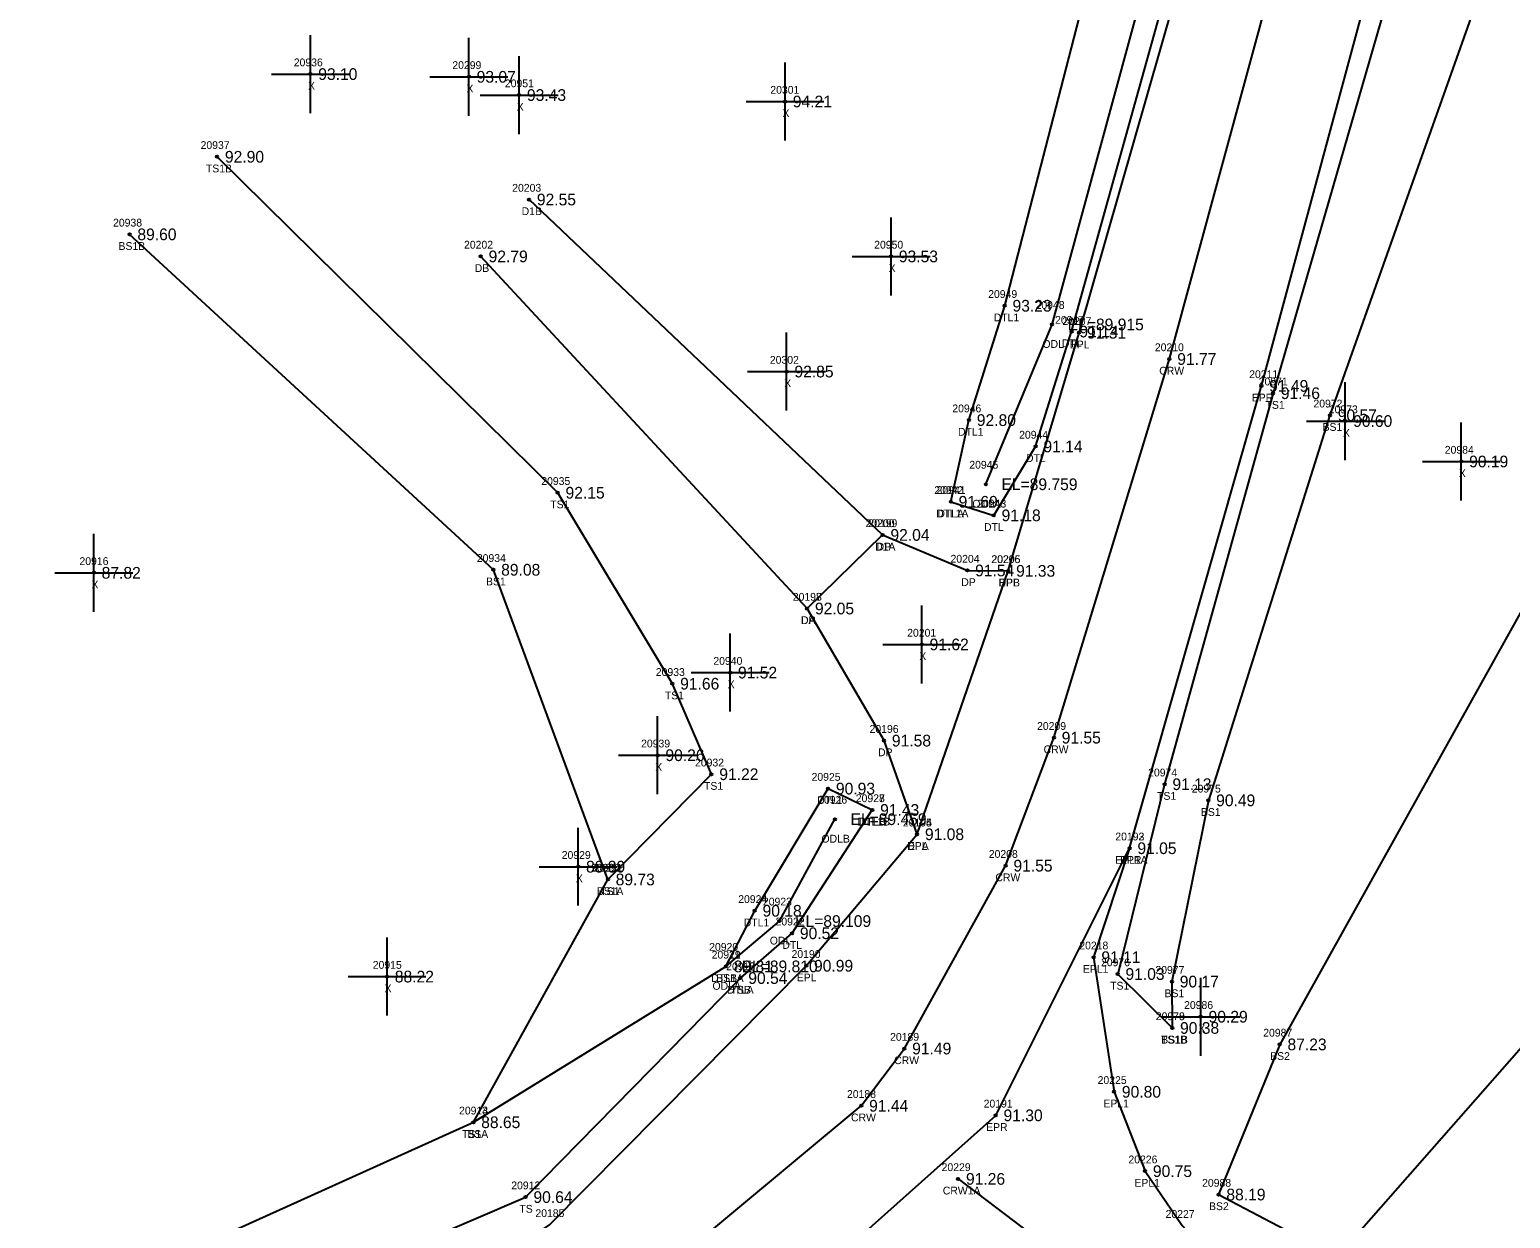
# Model space of a CAD drawing. Extents: x 2530197 to 2532051, y 935230 to 936631.
# Drawn here: x 2531647.6 to 2531837.5, y 936328 to 936480.5 of the extents above; entities that cross this region are included whole.
import ezdxf

# ---------------------------------------------------------------- set-up
doc = ezdxf.new("R2010")
doc.units = 0
for name, color, linetype in [('RD_DTM_BkLn1', 7, 'Continuous'), ('RD_DTM_BkLn2', 7, 'Continuous'), ('RD_DTM_BkLn_txCode', 7, 'Continuous'), ('RD_EX_Driveway', 7, 'Continuous'), ('RD_EX_Driveway_txCode', 7, 'Continuous'), ('RD_EX_H2O', 7, 'Continuous'), ('RD_EX_H2O_txCode', 7, 'Continuous'), ('RD_EX_Misc', 7, 'Continuous'), ('RD_EX_Misc_txCode', 7, 'Continuous'), ('RD_EX_Road', 7, 'Continuous'), ('RD_EX_Road_txCode', 7, 'Continuous'), ('RD_EX_TX_Driveway_ELEV', 7, 'Continuous'), ('RD_EX_TX_H2O_ELEV', 7, 'Continuous'), ('RD_EX_TX_Misc_ELEV', 7, 'Continuous'), ('RD_EX_TX_Road_ELEV', 7, 'Continuous'), ('RD_HC_Survey_ELEV', 7, 'Continuous'), ('RD_HC_Survey_txCode', 7, 'Continuous'), ('RD_SMD_Locator', 7, 'Continuous')]:
    doc.layers.add(name, color=color, linetype=linetype)

msp = doc.modelspace()

# ---------------------------------------------------------------- linework, layer by layer
at = {"layer": 'RD_DTM_BkLn1'}
for points in [[(2531175.16, 935992.09), (2531214.08, 936014.93), (2531297.2, 936064.16), (2531382.2, 936114.3), (2531466.12, 936163.77), (2531548.89, 936212.96), (2531632.55, 936261.89), (2531678, 936289.19), (2531722.34, 936315.93), (2531754.26, 936342.49), (2531759.78, 936349.83), (2531772.77, 936373.29), (2531778.96, 936389.71), (2531793.78, 936438.29), (2531813.65, 936511.36), (2531832.39, 936582.88)], [(2531766.68, 936333.11), (2531794.16, 936312.25), (2531844.23, 936274.13), (2531924.38, 936213.25), (2532005.14, 936152.12)]]:
    msp.add_lwpolyline(points, dxfattribs=at)
at = {"layer": 'RD_DTM_BkLn2'}
for points in [[(2531847.31, 936578.71), (2531828.5, 936507.99), (2531807.07, 936433.9), (2531793.16, 936383.74), (2531787.14, 936359.39), (2531794.14, 936352.47)], [(2531858.76, 936574.82), (2531840.28, 936504.17), (2531814.37, 936431.07), (2531798.77, 936381.67), (2531794.1, 936358.42), (2531794.14, 936352.47)], [(2531917.54, 936550.96), (2531882.37, 936485.34), (2531845.03, 936416.88), (2531807.92, 936350.36), (2531800.08, 936331.1), (2531815.28, 936323.11), (2531842.04, 936353.56), (2531870.4, 936350.41), (2531903.53, 936402.83), (2531942.77, 936461.82), (2531965.7, 936452.8), (2531970.35, 936457.79), (2531954.01, 936477.47), (2531964.77, 936498.69)], [(2531704.5, 936340.37), (2531721.75, 936371.52), (2531735.04, 936385.02), (2531730.02, 936396.63), (2531715.32, 936421.13), (2531671.63, 936464.23)], [(2531721.75, 936371.52), (2531707.06, 936411.25), (2531660.4, 936454.28)], [(2531549.3, 936252.1), (2531614.51, 936292.5), (2531672.61, 936325.97), (2531704.5, 936340.37), (2531736.9, 936360.37)], [(2531551.68, 936248.23), (2531617.31, 936287.8), (2531672.2, 936319.81), (2531679.05, 936316.94), (2531711.2, 936330.77), (2531738.76, 936358.87)]]:
    msp.add_lwpolyline(points, dxfattribs=at)
at = {"layer": 'RD_EX_Driveway'}
for p, q in [((2531756.99, 936415.72), (2531711.64, 936458.75)), ((2531747.31, 936406.28), (2531705.45, 936451.45))]:
    msp.add_line(p, q, dxfattribs=at)
msp.add_lwpolyline([(2531761.42, 936377.32), (2531757.18, 936389.33), (2531747.31, 936406.28), (2531756.99, 936415.72), (2531767.86, 936411.16), (2531773.11, 936411.11)], dxfattribs=at)
at = {"layer": 'RD_EX_H2O'}
for points in [[(2531765.74, 936419.97), (2531768.07, 936430.45), (2531772.65, 936445.12), (2531791.42, 936517.8), (2531810.23, 936589.19)], [(2531765.74, 936419.97), (2531771.25, 936418.23), (2531776.62, 936427.07), (2531781.23, 936441.81), (2531801.62, 936515.08), (2531818.73, 936586.25)], [(2531770.23, 936422.22), (2531778.73, 936442.72), (2531798.67, 936515.95), (2531816.58, 936587.11)], [(2531736.9, 936360.37), (2531740.59, 936367.5), (2531750, 936383.18), (2531755.67, 936380.44)], [(2531736.9, 936360.37), (2531743.76, 936366.18), (2531750.87, 936379.25)], [(2531738.76, 936358.87), (2531745.38, 936364.62), (2531755.67, 936380.44)]]:
    msp.add_lwpolyline(points, dxfattribs=at)
at = {"layer": 'RD_EX_Misc'}
for p, q in [((2531683.6, 936469.84), (2531683.6, 936479.84)), ((2531703.92, 936469.49), (2531703.92, 936479.49)), ((2531710.37, 936467.15), (2531710.37, 936477.15)), ((2531744.47, 936466.32), (2531744.47, 936476.32)), ((2531678.6, 936474.84), (2531688.6, 936474.84)), ((2531698.92, 936474.49), (2531708.92, 936474.49)), ((2531705.37, 936472.15), (2531715.37, 936472.15)), ((2531739.47, 936471.32), (2531749.47, 936471.32)), ((2531758.07, 936446.45), (2531758.07, 936456.45)), ((2531753.07, 936451.45), (2531763.07, 936451.45)), ((2531744.68, 936431.68), (2531744.68, 936441.68)), ((2531739.68, 936436.68), (2531749.68, 936436.68)), ((2531816.34, 936425.33), (2531816.34, 936435.33)), ((2531811.34, 936430.33), (2531821.34, 936430.33)), ((2531831.22, 936420.14), (2531831.22, 936430.14)), ((2531826.22, 936425.14), (2531836.22, 936425.14)), ((2531655.82, 936405.86), (2531655.82, 936415.86)), ((2531650.82, 936410.86), (2531660.82, 936410.86)), ((2531762.02, 936396.67), (2531762.02, 936406.67)), ((2531737.44, 936393.06), (2531737.44, 936403.06)), ((2531757.02, 936401.67), (2531767.02, 936401.67)), ((2531732.44, 936398.06), (2531742.44, 936398.06)), ((2531728.13, 936382.46), (2531728.13, 936392.46)), ((2531723.13, 936387.46), (2531733.13, 936387.46)), ((2531717.95, 936368.16), (2531717.95, 936378.16)), ((2531712.95, 936373.16), (2531722.95, 936373.16)), ((2531693.42, 936354.06), (2531693.42, 936364.06)), ((2531688.42, 936359.06), (2531698.42, 936359.06)), ((2531797.8, 936348.91), (2531797.8, 936358.91)), ((2531792.8, 936353.91), (2531802.8, 936353.91))]:
    msp.add_line(p, q, dxfattribs=at)
at = {"layer": 'RD_EX_Road'}
for points in [[(2531169.65, 936000.77), (2531208.79, 936024.95), (2531292.04, 936074.02), (2531376.24, 936123.7), (2531460.37, 936174.49), (2531542.92, 936223.44), (2531626.67, 936270.85), (2531672.4, 936298.39), (2531714.28, 936327.21), (2531747.19, 936360.45), (2531761.42, 936377.32), (2531773.11, 936411.11), (2531782.2, 936441.65), (2531803.17, 936514.76), (2531820.28, 936585.8)], [(2531180.82, 935982), (2531220.82, 936004.21), (2531303.54, 936053.39), (2531388.75, 936103.71), (2531472.27, 936152.98), (2531554.79, 936201.9), (2531638.11, 936250.92), (2531683.19, 936278.28), (2531730.37, 936304.55), (2531771.5, 936341.26), (2531788.67, 936375.53), (2531805.57, 936434.84), (2531825.53, 936508.74), (2531844.13, 936579.65)], [(2531788.67, 936375.53), (2531784.05, 936361.55), (2531786.68, 936344.28), (2531790.66, 936334.1), (2531795.41, 936327.11), (2531801.08, 936320.84), (2531849.6, 936283.17), (2531876.01, 936264.22), (2531894.71, 936249.13), (2531930.69, 936221.59), (2532010.91, 936160.51)]]:
    msp.add_lwpolyline(points, dxfattribs=at)
at = {"layer": 'RD_SMD_Locator'}
for centre in [(2531683.6, 936474.84), (2531703.92, 936474.49), (2531710.37, 936472.15), (2531744.47, 936471.32), (2531671.63, 936464.23), (2531711.64, 936458.75), (2531660.4, 936454.28), (2531705.45, 936451.45), (2531758.07, 936451.45), (2531772.65, 936445.12), (2531778.73, 936442.72), (2531781.23, 936441.81), (2531782.2, 936441.65), (2531793.78, 936438.29), (2531744.68, 936436.68), (2531805.57, 936434.84), (2531807.07, 936433.9), (2531768.07, 936430.45), (2531814.37, 936431.07), (2531816.34, 936430.33), (2531776.62, 936427.07), (2531831.22, 936425.14), (2531715.32, 936421.13), (2531770.23, 936422.22), (2531765.74, 936419.97), (2531765.74, 936419.97), (2531771.25, 936418.23), (2531756.99, 936415.72), (2531756.99, 936415.72), (2531707.06, 936411.25), (2531655.82, 936410.86), (2531767.86, 936411.16), (2531773.11, 936411.11), (2531773.11, 936411.11), (2531747.31, 936406.28), (2531747.31, 936406.28), (2531762.02, 936401.67), (2531737.44, 936398.06), (2531730.02, 936396.63), (2531757.18, 936389.33), (2531778.96, 936389.71), (2531728.13, 936387.46), (2531735.04, 936385.02), (2531750, 936383.18), (2531793.16, 936383.74), (2531798.77, 936381.67), (2531750.87, 936379.25), (2531755.67, 936380.44), (2531755.67, 936380.44), (2531761.42, 936377.32), (2531761.42, 936377.32), (2531788.67, 936375.53), (2531788.67, 936375.53), (2531772.77, 936373.29), (2531717.95, 936373.16), (2531721.75, 936371.52), (2531721.75, 936371.52), (2531740.59, 936367.5), (2531743.76, 936366.18), (2531745.38, 936364.62), (2531736.9, 936360.37), (2531736.9, 936360.37), (2531736.9, 936360.37), (2531747.19, 936360.45), (2531784.05, 936361.55), (2531693.42, 936359.06), (2531738.76, 936358.87), (2531738.76, 936358.87), (2531787.14, 936359.39), (2531794.1, 936358.42), (2531794.14, 936352.47), (2531794.14, 936352.47), (2531797.8, 936353.91), (2531759.78, 936349.83), (2531807.92, 936350.36), (2531786.68, 936344.28), (2531754.26, 936342.49), (2531771.5, 936341.26), (2531704.5, 936340.37), (2531704.5, 936340.37), (2531790.66, 936334.1), (2531766.68, 936333.11), (2531711.2, 936330.77), (2531800.08, 936331.1)]:
    msp.add_circle(centre, 0.15, dxfattribs=at)

# ---------------------------------------------------------------- texts
at = {"layer": 'RD_DTM_BkLn_txCode'}
for s, p in [('20937', (2531669.51, 936465.23)), ('TS1B', (2531670.19, 936462.23)), ('20938', (2531658.28, 936455.28)), ('BS1B', (2531658.98, 936452.28)), ('20971', (2531805.23, 936434.9)), ('TS1', (2531806.11, 936431.9)), ('20972', (2531812.25, 936432.07)), ('BS1', (2531813.43, 936429.07)), ('20935', (2531713.21, 936422.13)), ('TS1', (2531714.36, 936419.13)), ('20934', (2531704.94, 936412.25)), ('BS1', (2531706.12, 936409.25)), ('20933', (2531727.9, 936397.63)), ('TS1', (2531729.06, 936394.63)), ('20932', (2531732.93, 936386.02)), ('20974', (2531791.05, 936384.74)), ('TS1', (2531734.08, 936383.02)), ('20975', (2531796.65, 936382.67)), ('TS1', (2531792.2, 936381.74)), ('BS1', (2531797.82, 936379.67)), ('20930', (2531719.6, 936372.52)), ('20931', (2531719.92, 936372.52)), ('BS1A', (2531720.32, 936369.52)), ('TS1', (2531720.79, 936369.52)), ('20919', (2531735.06, 936361.37)), ('20917', (2531736.93, 936359.87)), ('20976', (2531785, 936360.39)), ('20977', (2531791.98, 936359.42)), ('BSB', (2531735.65, 936358.37)), ('TS1', (2531786.18, 936357.39)), ('TSB', (2531737.49, 936356.87)), ('BS1', (2531793.15, 936356.42)), ('20978', (2531792.03, 936353.47)), ('20979', (2531792.03, 936353.47)), ('TS1B', (2531792.71, 936350.47)), ('BS1B', (2531792.73, 936350.47)), ('20987', (2531805.81, 936351.36)), ('BS2', (2531806.7, 936348.36)), ('20913', (2531702.66, 936341.37)), ('20914', (2531702.66, 936341.37)), ('TS1A', (2531703.05, 936338.37)), ('BS', (2531703.72, 936338.37)), ('20912', (2531709.36, 936331.77)), ('20988', (2531797.97, 936332.1)), ('TS', (2531710.4, 936328.77)), ('BS2', (2531798.86, 936329.1))]:
    msp.add_text(s, height=1, dxfattribs=at).set_placement(p)
at = {"layer": 'RD_EX_Driveway_txCode'}
for s, p in [('20203', (2531709.48, 936459.75)), ('D1B', (2531710.69, 936456.75)), ('20202', (2531703.3, 936452.45)), ('DB', (2531704.67, 936449.45)), ('20200', (2531754.8, 936416.72)), ('20199', (2531755.16, 936416.72)), ('D1A', (2531756.03, 936413.72)), ('DP', (2531756.21, 936413.72)), ('20204', (2531765.7, 936412.16)), ('20205', (2531770.96, 936412.11)), ('DP', (2531767.08, 936409.16)), ('DPB', (2531771.86, 936409.11)), ('20197', (2531745.47, 936407.28)), ('20198', (2531745.47, 936407.28)), ('DA', (2531746.51, 936404.28)), ('DP', (2531746.53, 936404.28)), ('20196', (2531755.32, 936390.33)), ('DP', (2531756.4, 936387.33)), ('20195', (2531759.59, 936378.32)), ('DPA', (2531760.15, 936375.32))]:
    msp.add_text(s, height=1, dxfattribs=at).set_placement(p)
at = {"layer": 'RD_EX_H2O_txCode'}
for s, p in [('20949', (2531770.53, 936446.12)), ('20948', (2531776.61, 936444.72)), ('DTL1', (2531771.24, 936443.12)), ('20947', (2531779.11, 936442.81)), ('ODL', (2531777.49, 936439.72)), ('DTL', (2531779.99, 936439.81)), ('20946', (2531765.93, 936431.45)), ('DTL1', (2531766.66, 936428.45)), ('20944', (2531774.5, 936428.07)), ('20945', (2531768.11, 936424.22)), ('DTL', (2531775.38, 936425.07)), ('20942', (2531763.62, 936420.97)), ('20941', (2531763.91, 936420.97)), ('ODLA', (2531768.5, 936419.22)), ('20943', (2531769.13, 936419.23)), ('DTL1A', (2531763.84, 936417.97)), ('DTLA', (2531764.01, 936417.97)), ('DTL', (2531770, 936416.23)), ('20925', (2531747.88, 936384.18)), ('DTL1', (2531748.59, 936381.18)), ('20926', (2531748.72, 936381.25)), ('20927', (2531753.55, 936381.44)), ('20928', (2531753.55, 936381.44)), ('DTL1B', (2531753.78, 936378.44)), ('DTLB', (2531753.95, 936378.44)), ('ODLB', (2531749.15, 936376.25)), ('20924', (2531738.47, 936368.5)), ('20923', (2531741.64, 936368.18)), ('DTL1', (2531739.18, 936365.5)), ('20922', (2531743.26, 936365.62)), ('ODL', (2531742.52, 936363.18)), ('20920', (2531734.74, 936362.37)), ('20921', (2531735.06, 936361.37)), ('DTL', (2531744.13, 936362.62)), ('20918', (2531736.93, 936359.87)), ('DTL1A', (2531735, 936358.37)), ('ODLA', (2531735.17, 936357.37)), ('DTLA', (2531737.03, 936356.87))]:
    msp.add_text(s, height=1, dxfattribs=at).set_placement(p)
at = {"layer": 'RD_EX_Misc_txCode'}
for s, p in [('20936', (2531681.46, 936475.84)), ('20299', (2531701.8, 936475.49)), ('20951', (2531708.54, 936473.15)), ('X', (2531683.29, 936472.84)), ('X', (2531703.61, 936472.49)), ('20301', (2531742.59, 936472.32)), ('X', (2531710.06, 936470.15)), ('X', (2531744.15, 936469.32)), ('20950', (2531755.91, 936452.45)), ('X', (2531757.76, 936449.45)), ('20302', (2531742.53, 936437.68)), ('X', (2531744.37, 936434.68)), ('20973', (2531814.22, 936431.33)), ('X', (2531816.03, 936428.33)), ('20984', (2531829.1, 936426.14)), ('X', (2531830.9, 936423.14)), ('20916', (2531653.97, 936411.86)), ('X', (2531655.51, 936408.86)), ('20201', (2531760.14, 936402.67)), ('20940', (2531735.28, 936399.06)), ('X', (2531761.7, 936399.67)), ('X', (2531737.12, 936396.06)), ('20939', (2531726.01, 936388.46)), ('X', (2531727.82, 936385.46)), ('20929', (2531715.83, 936374.16)), ('X', (2531717.64, 936371.16)), ('20915', (2531691.59, 936360.06)), ('X', (2531693.11, 936357.06)), ('20986', (2531795.66, 936354.91)), ('X', (2531797.49, 936351.91))]:
    msp.add_text(s, height=1, dxfattribs=at).set_placement(p)
at = {"layer": 'RD_EX_Road_txCode'}
for s, p in [('20207', (2531780.05, 936442.65)), ('EPL', (2531781, 936439.65)), ('20211', (2531804.01, 936435.84)), ('EPR', (2531804.34, 936432.84)), ('20206', (2531770.93, 936412.11)), ('EPL', (2531771.91, 936409.11)), ('20194', (2531759.59, 936378.32)), ('20192', (2531786.84, 936376.53)), ('20193', (2531786.84, 936376.53)), ('EPL', (2531760.22, 936375.32)), ('EPL1A', (2531786.81, 936373.53)), ('EPR', (2531787.44, 936373.53)), ('20190', (2531745.31, 936361.45)), ('20218', (2531782.22, 936362.55)), ('EPL1', (2531782.68, 936359.55)), ('EPL', (2531745.98, 936358.45)), ('20225', (2531784.57, 936345.28)), ('20191', (2531769.95, 936342.26)), ('EPL1', (2531785.31, 936342.28)), ('EPR', (2531770.27, 936339.26)), ('20226', (2531788.52, 936335.1)), ('EPL1', (2531789.29, 936332.1)), ('20185', (2531712.45, 936328.21)), ('20227', (2531793.29, 936328.11))]:
    msp.add_text(s, height=1, dxfattribs=at).set_placement(p)
at = {"layer": 'RD_EX_TX_Driveway_ELEV'}
for s, p in [('92.55', (2531712.64, 936458)), ('92.79', (2531706.45, 936450.7)), ('92.04', (2531757.99, 936414.97)), ('92.04', (2531757.99, 936414.97)), ('91.54', (2531768.86, 936410.41)), ('91.33', (2531774.11, 936410.36)), ('92.05', (2531748.31, 936405.53)), ('92.05', (2531748.31, 936405.53)), ('91.58', (2531758.18, 936388.58)), ('91.08', (2531762.42, 936376.57))]:
    msp.add_text(s, height=1.5, dxfattribs=at).set_placement(p)
at = {"layer": 'RD_EX_TX_H2O_ELEV'}
for s, p in [('93.23', (2531773.65, 936444.37)), ('EL=89.915', (2531780.73, 936441.97)), ('91.14', (2531782.23, 936441.06)), ('92.80', (2531769.07, 936429.7)), ('91.14', (2531777.62, 936426.32)), ('EL=89.759', (2531772.23, 936421.47)), ('91.69', (2531766.74, 936419.22)), ('91.69', (2531766.74, 936419.22)), ('91.18', (2531772.25, 936417.48)), ('90.93', (2531751, 936382.43)), ('91.43', (2531756.67, 936379.69)), ('91.43', (2531756.67, 936379.69)), ('EL=89.459', (2531752.87, 936378.5)), ('90.18', (2531741.59, 936366.75)), ('EL=89.109', (2531745.76, 936365.43)), ('90.52', (2531746.38, 936363.87)), ('89.81', (2531737.9, 936359.62)), ('EL=89.810', (2531738.9, 936359.62)), ('90.54', (2531739.76, 936358.12))]:
    msp.add_text(s, height=1.5, dxfattribs=at).set_placement(p)
at = {"layer": 'RD_EX_TX_Misc_ELEV'}
for s, p in [('93.10', (2531684.6, 936474.09)), ('93.07', (2531704.92, 936473.74)), ('93.43', (2531711.37, 936471.4)), ('94.21', (2531745.47, 936470.57)), ('92.90', (2531672.63, 936463.48)), ('89.60', (2531661.4, 936453.53)), ('93.53', (2531759.07, 936450.7)), ('92.85', (2531745.68, 936435.93)), ('91.46', (2531808.07, 936433.15)), ('90.57', (2531815.37, 936430.32)), ('90.60', (2531817.34, 936429.58)), ('90.19', (2531832.22, 936424.39)), ('92.15', (2531716.32, 936420.38)), ('87.82', (2531656.82, 936410.11)), ('89.08', (2531708.06, 936410.5)), ('91.62', (2531763.02, 936400.92)), ('91.52', (2531738.44, 936397.31)), ('91.66', (2531731.02, 936395.88)), ('90.26', (2531729.13, 936386.71)), ('91.22', (2531736.04, 936384.27)), ('91.13', (2531794.16, 936382.99)), ('90.49', (2531799.77, 936380.92)), ('88.89', (2531718.95, 936372.41)), ('89.73', (2531722.75, 936370.77)), ('89.73', (2531722.75, 936370.77)), ('89.81', (2531737.9, 936359.62)), ('91.03', (2531788.14, 936358.64)), ('88.22', (2531694.42, 936358.31)), ('90.54', (2531739.76, 936358.12)), ('90.17', (2531795.1, 936357.67)), ('90.29', (2531798.8, 936353.16)), ('90.38', (2531795.14, 936351.72)), ('90.38', (2531795.14, 936351.72)), ('87.23', (2531808.92, 936349.61)), ('88.65', (2531705.5, 936339.62)), ('88.65', (2531705.5, 936339.62)), ('88.19', (2531801.08, 936330.35)), ('90.64', (2531712.2, 936330.02))]:
    msp.add_text(s, height=1.5, dxfattribs=at).set_placement(p)
at = {"layer": 'RD_EX_TX_Road_ELEV'}
for s, p in [('91.31', (2531783.2, 936440.9)), ('91.49', (2531806.57, 936434.09)), ('91.33', (2531774.11, 936410.36)), ('91.08', (2531762.42, 936376.57)), ('91.05', (2531789.67, 936374.78)), ('91.05', (2531789.67, 936374.78)), ('91.11', (2531785.05, 936360.8)), ('90.99', (2531748.19, 936359.7)), ('90.80', (2531787.68, 936343.53)), ('91.30', (2531772.5, 936340.51)), ('90.75', (2531791.66, 936333.35))]:
    msp.add_text(s, height=1.5, dxfattribs=at).set_placement(p)
at = {"layer": 'RD_HC_Survey_ELEV'}
for s, p in [('91.77', (2531794.78, 936437.54)), ('91.55', (2531779.96, 936388.96)), ('91.55', (2531773.77, 936372.54)), ('91.49', (2531760.78, 936349.08)), ('91.44', (2531755.26, 936341.74)), ('91.26', (2531767.68, 936332.36))]:
    msp.add_text(s, height=1.5, dxfattribs=at).set_placement(p)
at = {"layer": 'RD_HC_Survey_txCode'}
for s, p in [('20210', (2531791.91, 936439.29)), ('CRW', (2531792.47, 936436.29)), ('20209', (2531776.8, 936390.71)), ('CRW', (2531777.64, 936387.71)), ('20208', (2531770.61, 936374.29)), ('CRW', (2531771.46, 936371.29)), ('20189', (2531757.95, 936350.83)), ('CRW', (2531758.47, 936347.83)), ('20188', (2531752.42, 936343.49)), ('CRW', (2531752.94, 936340.49)), ('20229', (2531764.56, 936334.11)), ('CRW1A', (2531764.71, 936331.11))]:
    msp.add_text(s, height=1, dxfattribs=at).set_placement(p)

doc.saveas('drawing.dxf')
